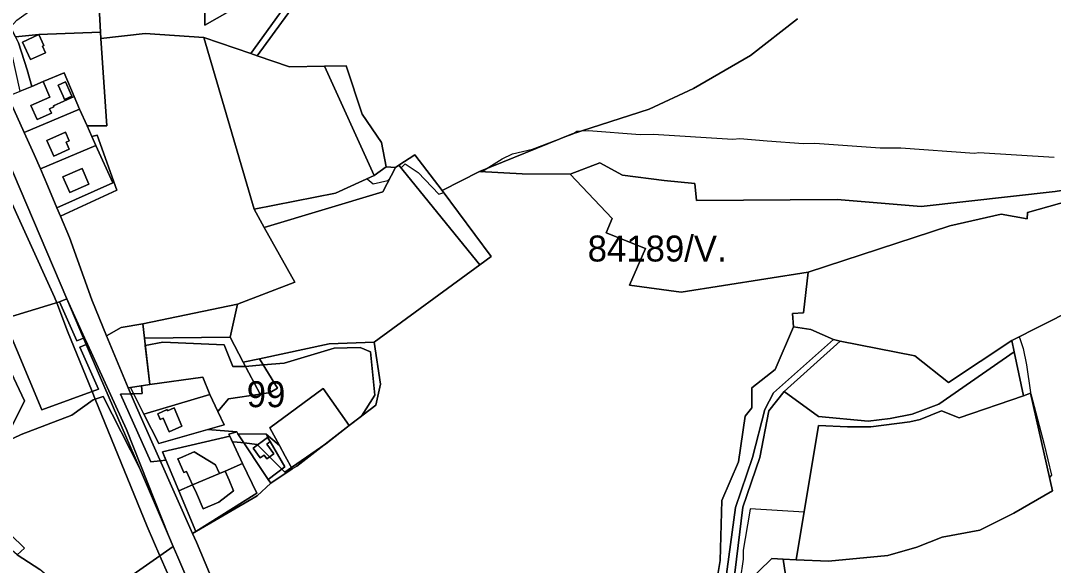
# Model space of a CAD drawing. Extents: x -477304 to -465429, y -1159113 to -1149210.
# Drawn here: x -475284 to -474688, y -1153923 to -1153609 of the extents above; entities that cross this region are included whole.
import ezdxf

# ---------------------------------------------------------------- set-up
doc = ezdxf.new("R2010")
doc.units = 0
for name, color, linetype in [('BPEJ_s', 7, 'Continuous'), ('ostatni_s', 7, 'Continuous'), ('PUPFL_s', 7, 'Continuous'), ('trav_porost_s', 7, 'Continuous'), ('voda_s', 7, 'Continuous'), ('zahrada_s', 7, 'Continuous')]:
    doc.layers.add(name, color=color, linetype=linetype)

msp = doc.modelspace()

# ---------------------------------------------------------------- linework, layer by layer
at = {"layer": 'BPEJ_s'}
for points in [[(-475121.02, -1153592.41), (-475146.02, -1153626.88), (-475146.6, -1153627.77), (-475147.42, -1153629.01), (-475128.78, -1153635.35), (-475108.55, -1153635), (-475079.85, -1153698.22), (-475083.88, -1153700.04), (-475080.5, -1153703), (-475072, -1153701), (-475070.93, -1153699.98), (-475067.57, -1153693.55), (-475065.63, -1153692.27)], [(-475121.02, -1153592.41), (-475146.02, -1153626.88), (-475146.6, -1153627.77), (-475147.42, -1153629.01), (-475128.78, -1153635.35), (-475108.55, -1153635), (-475079.85, -1153698.22), (-475083.88, -1153700.04), (-475080.5, -1153703), (-475072, -1153701), (-475070.93, -1153699.98), (-475067.57, -1153693.55), (-475065.63, -1153692.27), (-475064.4, -1153693.78), (-475062, -1153691.5), (-475054.5, -1153696.5), (-475042.5, -1153709), (-475039.72, -1153708.07), (-475040.64, -1153706.84), (-475019.08, -1153695.95), (-475017.81, -1153696.01), (-475015.26, -1153694.39), (-475006, -1153688.5), (-475000, -1153685.65), (-474988.47, -1153683.02), (-474970.67, -1153676.22), (-474965.48, -1153674.24), (-474965.37, -1153674.17), (-474965.21, -1153674.07), (-474962.92, -1153672.54), (-474959.9, -1153672.35), (-474956.11, -1153672.11), (-474926.33, -1153674.45), (-474918.67, -1153674.24), (-474872.7, -1153677.22), (-474868.66, -1153676.8), (-474852.96, -1153678.07), (-474831.85, -1153679.77), (-474825.26, -1153679.56), (-474787.59, -1153682.11), (-474775.68, -1153682.11), (-474733.12, -1153685.31), (-474730.57, -1153684.88), (-474687.16, -1153687.65)], [(-475065.63, -1153692.27), (-475064.4, -1153693.78), (-475062, -1153691.5), (-475054.5, -1153696.5), (-475042.5, -1153709), (-475039.72, -1153708.07), (-475040.64, -1153706.84), (-475019.08, -1153695.95), (-475017.81, -1153696.01), (-475015.26, -1153694.39), (-475006, -1153688.5), (-475000, -1153685.65), (-474988.47, -1153683.02), (-474970.67, -1153676.22), (-474965.48, -1153674.24), (-474965.37, -1153674.17), (-474965.21, -1153674.07), (-474962.92, -1153672.54), (-474959.9, -1153672.35), (-474956.11, -1153672.11), (-474926.33, -1153674.45), (-474918.67, -1153674.24), (-474872.7, -1153677.22), (-474868.66, -1153676.8), (-474852.96, -1153678.07), (-474831.85, -1153679.77), (-474825.26, -1153679.56), (-474787.59, -1153682.11), (-474775.68, -1153682.11), (-474733.12, -1153685.31), (-474730.57, -1153684.88), (-474687.16, -1153687.65)], [(-475190.52, -1153947.91), (-475203.65, -1153917.85), (-475211, -1153901), (-475241, -1153827.3), (-475242.78, -1153822.94), (-475257, -1153788), (-475263.28, -1153771.68), (-475264.5, -1153768.5), (-475295, -1153701.5)], [(-475295, -1153701.5), (-475264.5, -1153768.5), (-475263.28, -1153771.68), (-475257, -1153788), (-475242.78, -1153822.94), (-475241, -1153827.3), (-475211, -1153901), (-475203.65, -1153917.85), (-475190.52, -1153947.91)], [(-474659.32, -1153767.19), (-474707.66, -1153791.56), (-474707.16, -1153791.7), (-474705.03, -1153798.08), (-474703.12, -1153807.44), (-474700.78, -1153823.61), (-474700.67, -1153823.98), (-474700.59, -1153824.36), (-474692.95, -1153853.47), (-474688.65, -1153871.28), (-474689.85, -1153872.61), (-474688.14, -1153880.3), (-474710.35, -1153893.29), (-474730.02, -1153903.05), (-474751.79, -1153907.13), (-474766.41, -1153912.91), (-474783.13, -1153917.58), (-474817.54, -1153920.94), (-474836.11, -1153920.21), (-474831.55, -1153892.73), (-474862.73, -1153890.78), (-474863.13, -1153893.19), (-474866.75, -1153914.68), (-474866.75, -1153919.79), (-474868.45, -1153931.71)], [(-474659.32, -1153767.19), (-474707.66, -1153791.56), (-474707.16, -1153791.7), (-474705.03, -1153798.08), (-474703.12, -1153807.44), (-474700.78, -1153823.61), (-474700.67, -1153823.98), (-474700.59, -1153824.36), (-474692.95, -1153853.47), (-474688.65, -1153871.28), (-474689.85, -1153872.61), (-474688.14, -1153880.3), (-474710.35, -1153893.29), (-474730.02, -1153903.05), (-474751.79, -1153907.13), (-474766.41, -1153912.91), (-474783.13, -1153917.58), (-474817.54, -1153920.94), (-474836.11, -1153920.21), (-474831.55, -1153892.73), (-474862.73, -1153890.78), (-474863.13, -1153893.19), (-474866.75, -1153914.68), (-474866.75, -1153919.79), (-474868.45, -1153931.71)]]:
    msp.add_lwpolyline(points, dxfattribs=at)
for points in [[(-475166.5, -1153796), (-475161.5, -1153808.5), (-475154.5, -1153808.5), (-475154.36, -1153808.49), (-475144.04, -1153807.57), (-475132, -1153806.5), (-475103, -1153798), (-475088, -1153797.5), (-475082, -1153800), (-475079.5, -1153825), (-475087.19, -1153837.21), (-475094.29, -1153842.65), (-475107.85, -1153853.1), (-475127.69, -1153866.86), (-475131.5, -1153869.5), (-475133.2, -1153867.8), (-475140.35, -1153860.65), (-475147.26, -1153853.74), (-475147.5, -1153853.5), (-475155.1, -1153852.66), (-475161, -1153852), (-475161.7, -1153852.22), (-475163.36, -1153848.67), (-475202.25, -1153857.8), (-475200.22, -1153862.65), (-475203.46, -1153862.96), (-475209, -1153863.5), (-475226.5, -1153824.5), (-475220.5, -1153824.26), (-475218.92, -1153824.2), (-475214, -1153824), (-475214.33, -1153819.61), (-475209.54, -1153818.83), (-475212.12, -1153796.31), (-475202, -1153794.5)], [(-475166.5, -1153796), (-475202, -1153794.5), (-475212.12, -1153796.31), (-475209.54, -1153818.83), (-475214.33, -1153819.61), (-475214, -1153824), (-475218.92, -1153824.2), (-475220.5, -1153824.26), (-475226.5, -1153824.5), (-475209, -1153863.5), (-475203.46, -1153862.96), (-475200.22, -1153862.65), (-475202.25, -1153857.8), (-475163.36, -1153848.67), (-475161.7, -1153852.22), (-475161, -1153852), (-475155.1, -1153852.66), (-475147.5, -1153853.5), (-475147.26, -1153853.74), (-475140.35, -1153860.65), (-475133.2, -1153867.8), (-475131.5, -1153869.5), (-475127.69, -1153866.86), (-475107.85, -1153853.1), (-475094.29, -1153842.65), (-475087.19, -1153837.21), (-475079.5, -1153825), (-475082, -1153800), (-475088, -1153797.5), (-475103, -1153798), (-475132, -1153806.5), (-475144.04, -1153807.57), (-475154.36, -1153808.49), (-475154.5, -1153808.5), (-475161.5, -1153808.5)]]:
    msp.add_lwpolyline(points, close=True, dxfattribs=at)
at = {"layer": 'ostatni_s'}
for points in [[(-475290.02, -1153612.53), (-475287.1, -1153618.15), (-475285.33, -1153621.54), (-475280.39, -1153637.1), (-475277.76, -1153646.69), (-475284.35, -1153649.44), (-475289.03, -1153628.38), (-475292.9, -1153618.33), (-475291.27, -1153613.88)], [(-475278.47, -1153631.17), (-475283.16, -1153621.13), (-475273.55, -1153616.81), (-475270.68, -1153623.06), (-475271.58, -1153623.5), (-475269.84, -1153627.28)], [(-475264.92, -1153658.51), (-475267.43, -1153659.64), (-475266.32, -1153662.1), (-475274.55, -1153665.81), (-475278.18, -1153657.75), (-475267.3, -1153652.85), (-475271.07, -1153643.9), (-475259.03, -1153638.88), (-475253.19, -1153652.58), (-475265.15, -1153657.96)], [(-475255.42, -1153650.54), (-475254.61, -1153652.37), (-475258.86, -1153654.24), (-475259.64, -1153652.44), (-475262.51, -1153646.01), (-475258.25, -1153644.16)], [(-475258.86, -1153654.24), (-475254.61, -1153652.37), (-475255.42, -1153650.54), (-475258.25, -1153644.16), (-475262.51, -1153646.01), (-475259.64, -1153652.44)], [(-475272.6, -1153694.38), (-475276.33, -1153686.11), (-475282.14, -1153673.38), (-475250.07, -1153659.88), (-475245.8, -1153669.52), (-475243.11, -1153675.6), (-475240.75, -1153680.92)], [(-475257.94, -1153678.96), (-475256.02, -1153678.09), (-475258.22, -1153673.08), (-475269.03, -1153677.99), (-475264.92, -1153687.03), (-475256.09, -1153683.02)], [(-475256.09, -1153683.02), (-475264.92, -1153687.03), (-475269.03, -1153677.99), (-475258.22, -1153673.08), (-475256.02, -1153678.09), (-475257.94, -1153678.96)], [(-475018.91, -1153749.8), (-475065.63, -1153692.27), (-475056.45, -1153686.24), (-475040.64, -1153706.84), (-475012.31, -1153744.97)], [(-475248.66, -1153694.05), (-475244.68, -1153703.25), (-475255.82, -1153708.07), (-475259.8, -1153698.87)], [(-475143.43, -1153728.23), (-475149.26, -1153717.69), (-475102.17, -1153708.32), (-475079.85, -1153698.22), (-475072.94, -1153693.16), (-475067.57, -1153693.55), (-475074.91, -1153707.61)], [(-475257.5, -1153769.35), (-475247.2, -1153791.94), (-475247.81, -1153792.17)], [(-475261.64, -1153771.18), (-475251.68, -1153793.63), (-475247.81, -1153792.17), (-475246.27, -1153795.8), (-475250.03, -1153797.34), (-475239.24, -1153821.65), (-475271.98, -1153833.55), (-475293.81, -1153780.96)], [(-475247.2, -1153791.94), (-475245.57, -1153795.51), (-475246.27, -1153795.8), (-475247.81, -1153792.17)], [(-474810.81, -1153793.9), (-474767.6, -1153802.34), (-474748.19, -1153817.67), (-474711.61, -1153793.55), (-474710.21, -1153800.12), (-474753.78, -1153830.35), (-474769.14, -1153836.04), (-474781.92, -1153838.53), (-474794.59, -1153839.98), (-474823.21, -1153837.46), (-474843.05, -1153822.86)], [(-475238.66, -1153813.69), (-475246.27, -1153795.8), (-475245.57, -1153795.51), (-475223.07, -1153844.85), (-475198.64, -1153906.05), (-475215.58, -1153866.95)], [(-474823.24, -1153842.58), (-474836.11, -1153920.21), (-474843.64, -1153919.81), (-474850.18, -1153919.41), (-474873.34, -1153941.92), (-474866.85, -1153889.7), (-474857.12, -1153861.1), (-474851.93, -1153834.19), (-474843.05, -1153822.86), (-474823.21, -1153837.46), (-474794.59, -1153839.98), (-474781.92, -1153838.53), (-474769.14, -1153836.04), (-474753.78, -1153830.35), (-474710.21, -1153800.12), (-474704.82, -1153825.5), (-474742, -1153838.13), (-474752.18, -1153834.09), (-474764.45, -1153839.08), (-474770.49, -1153840.38), (-474793.05, -1153843.38), (-474806.42, -1153843.43)], [(-475220.72, -1153820.65), (-475209.54, -1153818.83), (-475178.99, -1153814.69), (-475174.82, -1153824.59), (-475212.93, -1153835.96)], [(-475221.94, -1153820.85), (-475220.72, -1153820.65), (-475212.93, -1153835.96), (-475204.41, -1153852.95), (-475176.04, -1153844.83), (-475159.2, -1153846.3), (-475163.9, -1153847.56), (-475163.36, -1153848.67), (-475202.25, -1153857.8), (-475192.84, -1153880.33), (-475182.95, -1153903.76), (-475184.89, -1153904.97), (-475214.25, -1153838.54), (-475218.52, -1153828.95)], [(-475212.93, -1153835.96), (-475174.82, -1153824.59), (-475170.15, -1153834.41), (-475166.52, -1153842.1), (-475176.04, -1153844.83), (-475204.41, -1153852.95)], [(-475199.54, -1153833.43), (-475204.98, -1153835.79), (-475203.56, -1153839.07), (-475201.85, -1153838.33), (-475198.44, -1153846.22), (-475190.96, -1153842.98), (-475195.51, -1153832.46), (-475199.26, -1153834.09)], [(-475195.51, -1153832.46), (-475190.96, -1153842.98), (-475198.44, -1153846.22), (-475201.85, -1153838.33), (-475203.56, -1153839.07), (-475204.98, -1153835.79), (-475199.54, -1153833.43), (-475199.26, -1153834.09)], [(-475147.44, -1153883.15), (-475184.89, -1153904.97), (-475182.95, -1153903.76), (-475147.79, -1153881.75), (-475155.95, -1153864.55), (-475163.36, -1153848.67), (-475163.9, -1153847.56), (-475159.2, -1153846.3), (-475158.59, -1153847.37), (-475141.1, -1153873.86), (-475139.69, -1153875.88)], [(-475142.32, -1153847.63), (-475139.93, -1153851.81), (-475141.54, -1153849.58), (-475149.89, -1153855.65), (-475145.74, -1153861.35), (-475143.55, -1153859.76), (-475142.02, -1153861.86), (-475137.89, -1153858.86), (-475141.95, -1153853.28), (-475139.93, -1153851.81), (-475131.5, -1153866.5), (-475141.1, -1153873.86), (-475158.59, -1153847.37)], [(-475134.66, -1153854.17), (-475131.35, -1153860.2), (-475127.23, -1153867.69), (-475139.69, -1153875.88), (-475141.1, -1153873.86), (-475131.5, -1153866.5), (-475139.93, -1153851.81), (-475142.32, -1153847.63)], [(-475137.89, -1153858.86), (-475142.02, -1153861.86), (-475143.55, -1153859.76), (-475145.74, -1153861.35), (-475149.89, -1153855.65), (-475141.54, -1153849.58), (-475139.93, -1153851.81), (-475141.95, -1153853.28)], [(-475169.35, -1153870.28), (-475184.78, -1153876.88), (-475188.31, -1153869.11), (-475189.82, -1153869.78), (-475193.34, -1153861.91), (-475191.83, -1153861.23), (-475183.98, -1153857.72), (-475171.49, -1153865.27), (-475169.5, -1153869.91)], [(-475161.19, -1153880.28), (-475169.71, -1153886.82), (-475178.71, -1153890.68), (-475182.65, -1153881.73), (-475184.78, -1153876.88), (-475169.35, -1153870.28), (-475166.06, -1153868.88), (-475163.78, -1153874.21)]]:
    msp.add_lwpolyline(points, close=True, dxfattribs=at)
for points in [[(-475291.5, -1153652.42), (-475282.14, -1153673.38), (-475276.33, -1153686.11), (-475272.6, -1153694.38), (-475268.43, -1153704.38), (-475263.19, -1153716.9), (-475261.21, -1153721.59)], [(-475160.33, -1153995.29), (-475193.42, -1153918.67), (-475195.98, -1153912.48), (-475198.64, -1153906.05), (-475223.07, -1153844.85), (-475245.57, -1153795.51), (-475247.2, -1153791.94), (-475257.5, -1153769.35), (-475295.94, -1153678.9)], [(-475261.21, -1153721.59), (-475256.01, -1153733.93), (-475243, -1153769.96), (-475234.63, -1153790.84), (-475221.94, -1153820.85), (-475218.52, -1153828.95), (-475214.25, -1153838.54), (-475184.89, -1153904.97), (-475182.65, -1153910.04), (-475144.98, -1153999.55)], [(-474883.06, -1153939.01), (-474880.06, -1153920.54), (-474879.15, -1153885.96), (-474869.45, -1153863.49), (-474865.52, -1153837.18), (-474861.75, -1153832.37), (-474861.7, -1153820.82), (-474848.17, -1153810.28), (-474837.76, -1153785.62), (-474827.68, -1153787.16), (-474814.55, -1153792.85), (-474849.16, -1153823.66), (-474854.3, -1153833.39), (-474861.28, -1153861.05), (-474871.09, -1153889.86), (-474878, -1153939.78)], [(-474878, -1153939.78), (-474871.09, -1153889.86), (-474861.28, -1153861.05), (-474854.3, -1153833.39), (-474849.16, -1153823.66), (-474814.55, -1153792.85), (-474810.81, -1153793.9), (-474843.05, -1153822.86), (-474851.93, -1153834.19), (-474857.12, -1153861.1), (-474866.85, -1153889.7), (-474873.34, -1153941.92)]]:
    msp.add_lwpolyline(points, dxfattribs=at)
at = {"layer": 'PUPFL_s'}
for points in [[(-474675.82, -1153563.86), (-474654.47, -1153625.24), (-474612.18, -1153694.54), (-474642.19, -1153702.55), (-474668.1, -1153704.59), (-474686.52, -1153707.45), (-474763.99, -1153716.02), (-474812.44, -1153711.97), (-474893.73, -1153712.54), (-474894.75, -1153702.75), (-474912.46, -1153701.11), (-474936.42, -1153698.02), (-474949.63, -1153690.86), (-474966.6, -1153697.31), (-474994.43, -1153697.21), (-475019.08, -1153695.95), (-474965.97, -1153674.31), (-474921, -1153659.79), (-474895.53, -1153647.89), (-474862.59, -1153628.77), (-474835.45, -1153607.68)], [(-474835.45, -1153607.68), (-474862.59, -1153628.77), (-474895.53, -1153647.89), (-474921, -1153659.79), (-474965.97, -1153674.31), (-475019.08, -1153695.95), (-475040.64, -1153706.84), (-475056.45, -1153686.24), (-475065.63, -1153692.27), (-475067.57, -1153693.55), (-475072.94, -1153693.16), (-475075.72, -1153679.13), (-475086.8, -1153662.73), (-475096.08, -1153634.79), (-475108.55, -1153635), (-475128.78, -1153635.35), (-475147.54, -1153628.97), (-475121.02, -1153592.41)], [(-474626.28, -1153946.71), (-474834.5, -1153980.48), (-474843.64, -1153919.81), (-474836.11, -1153920.21), (-474817.54, -1153920.94), (-474783.13, -1153917.58), (-474766.41, -1153912.91), (-474751.79, -1153907.13), (-474730.02, -1153903.05), (-474710.35, -1153893.29), (-474688.14, -1153880.3), (-474700.67, -1153823.98), (-474704.82, -1153825.5), (-474710.21, -1153800.12), (-474711.61, -1153793.55), (-474659.32, -1153767.19)], [(-474873.34, -1153941.92), (-474850.18, -1153919.41), (-474843.64, -1153919.81), (-474834.5, -1153980.48)]]:
    msp.add_lwpolyline(points, dxfattribs=at)
for points in [[(-475072.94, -1153693.16), (-475079.85, -1153698.22), (-475108.55, -1153635), (-475096.08, -1153634.79), (-475086.8, -1153662.73), (-475075.72, -1153679.13)], [(-475145.68, -1153824.43), (-475163.99, -1153827.18), (-475170.15, -1153834.41), (-475174.82, -1153824.59), (-475178.99, -1153814.69), (-475209.54, -1153818.83), (-475212.6, -1153792.16), (-475163.12, -1153791.49), (-475155.68, -1153806.07)], [(-475170.15, -1153834.41), (-475163.99, -1153827.18), (-475145.68, -1153824.43), (-475140.09, -1153823.55), (-475135.77, -1153820.99), (-475146.22, -1153804.03), (-475105.99, -1153795.34), (-475079.94, -1153794.52), (-475076.27, -1153818.64), (-475078.97, -1153830.92), (-475094.29, -1153842.65), (-475109.45, -1153821.29), (-475140.28, -1153843.93), (-475134.66, -1153854.17), (-475142.32, -1153847.63), (-475158.59, -1153847.37), (-475159.2, -1153846.3), (-475176.04, -1153844.83), (-475166.52, -1153842.1)], [(-475135.77, -1153820.99), (-475140.09, -1153823.55), (-475145.68, -1153824.43), (-475155.68, -1153806.07), (-475146.22, -1153804.03)], [(-475094.29, -1153842.65), (-475124.57, -1153865.98), (-475127.23, -1153867.69), (-475131.35, -1153860.2), (-475134.66, -1153854.17), (-475140.28, -1153843.93), (-475109.45, -1153821.29)]]:
    msp.add_lwpolyline(points, close=True, dxfattribs=at)
at = {"layer": 'trav_porost_s'}
for points in [[(-475147.54, -1153628.97), (-475151.09, -1153627.76), (-475124.5, -1153590.75), (-475119.47, -1153580.22), (-475119.33, -1153578.07), (-475115.51, -1153550.4), (-475120.66, -1153525.96), (-475117.3, -1153524.97), (-475112.56, -1153551.94), (-475115.67, -1153577.59), (-475116.11, -1153581.58), (-475121.02, -1153592.41)], [(-475115.51, -1153550.4), (-475119.33, -1153578.07), (-475177.74, -1153611.24), (-475177.22, -1153559.5), (-475168.34, -1153555.54), (-475155.98, -1153543.74), (-475145.8, -1153535.71), (-475126.37, -1153527.64), (-475120.66, -1153525.96)], [(-475177.74, -1153611.24), (-475119.33, -1153578.07), (-475119.47, -1153580.22), (-475124.5, -1153590.75), (-475151.09, -1153627.76), (-475178.33, -1153618.5), (-475212.23, -1153616.22), (-475237.76, -1153619.12), (-475238.02, -1153615.32), (-475239.41, -1153589.93), (-475242.7, -1153580.69), (-475239.09, -1153579.19), (-475212.03, -1153567.45), (-475190.2, -1153563.38), (-475177.22, -1153559.5)], [(-475268.33, -1153595.35), (-475250.01, -1153583.72), (-475242.7, -1153580.69), (-475239.41, -1153589.93), (-475238.02, -1153615.32), (-475273.55, -1153616.81), (-475287.1, -1153618.15), (-475290.02, -1153612.53), (-475286.27, -1153608.49)], [(-475278.47, -1153631.17), (-475269.84, -1153627.28), (-475271.58, -1153623.5), (-475270.68, -1153623.06), (-475273.55, -1153616.81), (-475238.02, -1153615.32), (-475237.76, -1153619.12), (-475234.27, -1153669.52), (-475245.8, -1153669.52), (-475250.07, -1153659.88), (-475253.19, -1153652.58), (-475259.03, -1153638.88), (-475271.07, -1153643.9), (-475277.76, -1153646.69), (-475280.39, -1153637.1), (-475285.33, -1153621.54), (-475287.1, -1153618.15), (-475273.55, -1153616.81), (-475283.16, -1153621.13)], [(-475234.27, -1153669.52), (-475237.76, -1153619.12), (-475212.23, -1153616.22), (-475178.33, -1153618.5), (-475149.26, -1153717.69), (-475143.43, -1153728.23), (-475125.7, -1153759.77), (-475158.82, -1153772.41), (-475213.55, -1153783.85), (-475226.06, -1153786), (-475234.63, -1153790.84), (-475243, -1153769.96), (-475256.01, -1153733.93), (-475261.21, -1153721.59), (-475228.64, -1153706.57), (-475239.85, -1153674.85), (-475243.11, -1153675.6), (-475245.8, -1153669.52)], [(-475151.09, -1153627.76), (-475147.54, -1153628.97), (-475128.78, -1153635.35), (-475108.55, -1153635), (-475079.85, -1153698.22), (-475102.17, -1153708.32), (-475149.26, -1153717.69), (-475178.33, -1153618.5)], [(-475336.78, -1153702.29), (-475328.73, -1153692.66), (-475328.73, -1153686.38), (-475332.17, -1153673.21), (-475301.26, -1153665.37), (-475295.94, -1153678.9), (-475257.5, -1153769.35), (-475261.64, -1153771.18), (-475293.81, -1153780.96), (-475299.68, -1153782.46), (-475318.68, -1153771.09), (-475336.69, -1153763.68), (-475345.52, -1153750.83), (-475355.74, -1153721.59), (-475355.72, -1153711.53), (-475346.36, -1153719.38), (-475346.4, -1153704.11)], [(-475240.75, -1153680.92), (-475243.11, -1153675.6), (-475239.85, -1153674.85), (-475228.64, -1153706.57), (-475261.21, -1153721.59), (-475263.19, -1153716.9), (-475230.88, -1153702.33)], [(-475143.43, -1153728.23), (-475074.91, -1153707.61), (-475067.57, -1153693.55), (-475065.63, -1153692.27), (-475018.91, -1153749.8), (-475079.94, -1153794.52), (-475105.99, -1153795.34), (-475146.22, -1153804.03), (-475155.68, -1153806.07), (-475163.12, -1153791.49), (-475158.82, -1153772.41), (-475125.7, -1153759.77)], [(-474717.65, -1153720.52), (-474747.34, -1153727.16), (-474829.16, -1153753.94), (-474902.61, -1153765.48), (-474932.32, -1153761.52), (-474923.1, -1153740.36), (-474945.99, -1153731.36), (-474942.37, -1153722.99), (-474966.6, -1153697.31), (-474949.63, -1153690.86), (-474936.42, -1153698.02), (-474912.46, -1153701.11), (-474894.75, -1153702.75), (-474893.73, -1153712.54), (-474812.44, -1153711.97), (-474763.99, -1153716.02), (-474686.52, -1153707.45), (-474668.1, -1153704.59), (-474642.19, -1153702.55), (-474702.48, -1153719.47), (-474702.78, -1153723.16)], [(-474634.76, -1153730.2), (-474630.77, -1153737.29), (-474643.45, -1153753.07), (-474659.32, -1153767.19), (-474711.61, -1153793.55), (-474748.19, -1153817.67), (-474767.6, -1153802.34), (-474810.81, -1153793.9), (-474814.55, -1153792.85), (-474827.68, -1153787.16), (-474837.76, -1153785.62), (-474838.21, -1153777.98), (-474831.97, -1153777.53), (-474829.16, -1153753.94), (-474747.34, -1153727.16), (-474717.65, -1153720.52), (-474702.78, -1153723.16), (-474702.48, -1153719.47), (-474642.19, -1153702.55)], [(-475257.5, -1153769.35), (-475247.81, -1153792.17), (-475251.68, -1153793.63), (-475261.64, -1153771.18)], [(-475212.6, -1153792.16), (-475213.55, -1153783.85), (-475158.82, -1153772.41), (-475163.12, -1153791.49)], [(-475281.86, -1153913.47), (-475286.07, -1153917.2), (-475304.69, -1153901.53), (-475317.83, -1153883.13), (-475316.44, -1153864.83), (-475306.89, -1153854.13), (-475289.22, -1153843.24), (-475281.91, -1153828.38), (-475294.04, -1153802.48), (-475299.68, -1153782.46), (-475293.81, -1153780.96), (-475271.98, -1153833.55), (-475239.24, -1153821.65), (-475250.03, -1153797.34), (-475246.27, -1153795.8), (-475238.66, -1153813.69), (-475215.58, -1153866.95), (-475236.4, -1153825.75), (-475242.32, -1153827.75), (-475254.64, -1153836.55), (-475283.88, -1153847.76), (-475304.66, -1153857.55), (-475311.76, -1153879.17), (-475306.6, -1153889.58)], [(-475221.94, -1153820.85), (-475234.63, -1153790.84), (-475226.06, -1153786), (-475213.55, -1153783.85), (-475212.6, -1153792.16), (-475209.54, -1153818.83), (-475220.72, -1153820.65)], [(-475306.6, -1153889.58), (-475311.76, -1153879.17), (-475304.66, -1153857.55), (-475283.88, -1153847.76), (-475254.64, -1153836.55), (-475242.32, -1153827.75), (-475236.4, -1153825.75), (-475215.58, -1153866.95), (-475198.64, -1153906.05), (-475195.98, -1153912.48), (-475244.74, -1153946.61), (-475231.26, -1153963.94), (-475247.12, -1153947.87), (-475273.09, -1153925.68), (-475286.07, -1153917.2), (-475281.86, -1153913.47)], [(-474700.67, -1153823.98), (-474688.14, -1153880.3), (-474710.35, -1153893.29), (-474730.02, -1153903.05), (-474751.79, -1153907.13), (-474766.41, -1153912.91), (-474783.13, -1153917.58), (-474817.54, -1153920.94), (-474836.11, -1153920.21), (-474823.24, -1153842.58), (-474806.42, -1153843.43), (-474793.05, -1153843.38), (-474770.49, -1153840.38), (-474764.45, -1153839.08), (-474752.18, -1153834.09), (-474742, -1153838.13), (-474704.82, -1153825.5)], [(-475202.25, -1153857.8), (-475163.36, -1153848.67), (-475155.95, -1153864.55), (-475166.06, -1153868.88), (-475169.35, -1153870.28), (-475169.5, -1153869.91), (-475171.49, -1153865.27), (-475183.98, -1153857.72), (-475191.83, -1153861.23), (-475193.34, -1153861.91), (-475189.82, -1153869.78), (-475188.31, -1153869.11), (-475184.78, -1153876.88), (-475192.84, -1153880.33)], [(-475166.06, -1153868.88), (-475155.95, -1153864.55), (-475147.79, -1153881.75), (-475182.95, -1153903.76), (-475192.84, -1153880.33), (-475184.78, -1153876.88), (-475182.65, -1153881.73), (-475178.71, -1153890.68), (-475169.71, -1153886.82), (-475161.19, -1153880.28), (-475163.78, -1153874.21)], [(-475158.76, -1153998.29), (-475230.99, -1154031.16), (-475231.34, -1154026.92), (-475228.47, -1154006.11), (-475223.86, -1153983.73), (-475226.12, -1153974.33), (-475231.26, -1153963.94), (-475244.74, -1153946.61), (-475195.98, -1153912.48), (-475193.42, -1153918.67), (-475160.33, -1153995.29)]]:
    msp.add_lwpolyline(points, close=True, dxfattribs=at)
msp.add_lwpolyline([(-475144.98, -1153999.55), (-475182.65, -1153910.04), (-475184.89, -1153904.97), (-475147.44, -1153883.15), (-475139.69, -1153875.88), (-475127.23, -1153867.69), (-475124.57, -1153865.98), (-475094.29, -1153842.65), (-475078.97, -1153830.92), (-475076.27, -1153818.64), (-475079.94, -1153794.52), (-475018.91, -1153749.8), (-475012.31, -1153744.97), (-475040.64, -1153706.84), (-475019.08, -1153695.95), (-474994.43, -1153697.21), (-474966.6, -1153697.31), (-474942.37, -1153722.99), (-474945.99, -1153731.36), (-474923.1, -1153740.36), (-474932.32, -1153761.52), (-474902.61, -1153765.48), (-474829.16, -1153753.94), (-474831.97, -1153777.53), (-474838.21, -1153777.98), (-474837.76, -1153785.62), (-474848.17, -1153810.28), (-474861.7, -1153820.82), (-474861.75, -1153832.37), (-474865.52, -1153837.18), (-474869.45, -1153863.49), (-474879.15, -1153885.96), (-474880.06, -1153920.54), (-474883.06, -1153939.01)], dxfattribs=at)
at = {"layer": 'voda_s'}
for points in [[(-475294.04, -1153802.48), (-475281.91, -1153828.38), (-475289.22, -1153843.24)], [(-475286.07, -1153917.2), (-475273.09, -1153925.68)]]:
    msp.add_lwpolyline(points, dxfattribs=at)
at = {"layer": 'zahrada_s'}
for points in [[(-475291.5, -1153652.42), (-475284.35, -1153649.44), (-475277.76, -1153646.69), (-475271.07, -1153643.9), (-475267.3, -1153652.85), (-475278.18, -1153657.75), (-475274.55, -1153665.81), (-475266.32, -1153662.1), (-475267.43, -1153659.64), (-475264.92, -1153658.51), (-475265.15, -1153657.96), (-475253.19, -1153652.58), (-475250.07, -1153659.88), (-475282.14, -1153673.38)], [(-475263.19, -1153716.9), (-475268.43, -1153704.38), (-475272.6, -1153694.38), (-475240.75, -1153680.92), (-475230.88, -1153702.33)], [(-475259.8, -1153698.87), (-475255.82, -1153708.07), (-475244.68, -1153703.25), (-475248.66, -1153694.05)]]:
    msp.add_lwpolyline(points, close=True, dxfattribs=at)

# ---------------------------------------------------------------- texts
at = {"layer": 'BPEJ_s'}
for s, p in [('84189/V.', (-474956.58, -1153747.85)), ('99', (-475153.52, -1153832))]:
    msp.add_text(s, height=15, dxfattribs=at).set_placement(p)

doc.saveas('drawing.dxf')
